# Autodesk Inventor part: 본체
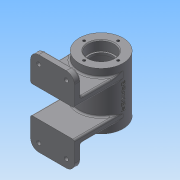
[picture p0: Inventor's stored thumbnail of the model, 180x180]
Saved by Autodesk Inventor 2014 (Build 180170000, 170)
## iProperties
Created: 2017-02
Part Number: 본체
Material: 일반
Document SubType Name: Modeling
Designer: owner
Density: 1 g/cm^3
Appearance: 기본값
Author: owner
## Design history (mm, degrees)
sketch "스케치1"
  geometry: L1 (27, 35)-(0, 35); L2 (0, 35)-(0, -35); L3 (0, -35)-(27, -35); L4 (27, -35)-(27, 35); 1 further point
  constraints: 8 end point, 2 parallel, 1 horizontal, 1 midpoint, 1 perpendicular
  dimensions: "d0" = 70 distance of L1.end L2.end; "d1" = 54 diameter of L4 L2; "d2" = 35 distance from line of point (0, 0) L1
revolve "회전1" sketch "스케치1" stored, may be unused: angle "d3" = 90 deg
node "작업 평면1"
sketch "스케치2"
  geometry: L1 (27, -52)-(-27, -52); L2 (-27, -52)-(-27, 52); L3 (-27, 52)-(27, 52); L4 (27, 52)-(27, -52); 1 further point
  constraints: 8 end point, 2 parallel, 1 horizontal, 1 perpendicular
  dimensions: "d5" = 54 distance between parallel lines of L4 L2; "d6" = 27 distance from line of L4 point (0, 0); "d7" = 52 distance from line of point (0, 0) L1; "d8" = 104 distance between parallel lines of L3 L1
extrude "돌출1" join sketch "스케치2" distance "d9" = 8; taper "d10" = 0 deg
sketch "스케치3"
  geometry: L1 (-27, 52)-(-27, -52) reference; L2 (27, -52)-(27, 52) reference; L3 (-27, 0)-(27, 0); L4 (-27, 17)-(27, 17); L5 (27, 17)-(27, -17); L6 (27, -17)-(-27, -17); L7 (-27, -17)-(-27, 17); 1 further point
  constraints: 10 end point, 2 midpoint, 2 parallel, 2 point on line, 1 horizontal, 1 perpendicular
  dimensions: "d11" = 17 distance from line of L4 point (0, 0); "d12" = 17 distance from line of L6 point (0, 0)
extrude "돌출2" cut sketch "스케치3" stored distance "d13" = 8; taper "d14" = 0 deg
sketch "스케치4"
  geometry: L1 (27, -52)-(27, -17) reference; L2 (-27, -17)-(27, -17); L3 (27, -17)-(27, -25); L4 (27, -25)-(-27, -25); L5 (-27, -25)-(-27, -17); 1 further point
  constraints: 8 end point, 2 parallel, 1 horizontal, 1 perpendicular, 1 point on line
  dimensions: "d15" = 8 distance between parallel lines of L2 L4
extrude "돌출3" join sketch "스케치4" stored distance "d16" = 8; taper "d17" = 0 deg
sketch "스케치5"
  geometry: L1 (-27, -35)-(27, -35) reference; L2 (-27, 35)-(27, 35) reference; L3 (0, -35)-(0, 35); L4 (16, 35)-(0, 35); L5 (0, 35)-(0, 23); L6 (0, 23)-(16, 23); L7 (16, 23)-(16, 35); L8 (0, 23)-(14, 23); L9 (14, 23)-(14, 20); L10 (14, 20)-(0, 20); L11 (0, 20)-(0, 23); L12 (0, 20)-(22, 20); L13 (22, 20)-(22, -20); L14 (22, -20)-(0, -20); L15 (0, -20)-(0, 20); L16 (0, -20)-(14, -20); L17 (14, -20)-(14, -23); L18 (14, -23)-(0, -23); L19 (0, -23)-(0, -20); L20 (0, -23)-(16, -23); L21 (16, -23)-(16, -35); L22 (16, -35)-(0, -35); L23 (0, -35)-(0, -23); 1 further point
  constraints: 42 end point, 10 parallel, 5 horizontal, 5 perpendicular, 3 point on line, 2 midpoint
  dimensions: "d18" = 32 diameter of L21 L3; "d19" = 44 diameter of L13 L3; "d20" = 12 distance between parallel lines of L22 L20; "d21" = 3 distance between parallel lines of L16 L20; "d22" = 28 diameter of L17 L3; "d23" = 40 distance between parallel lines of L10 L16; "d24" = 32 diameter of L7 L3; "d25" = 28 diameter of L9 L3; "d26" = 12 distance between parallel lines of L6 L4
revolve "회전2" sketch "스케치5" stored, may be unused: angle "d27" = 90 deg
fillet "모깎기1" dims "d28" = 10
sketch "스케치6" dims "d29" = 9, "d30" = 9
  geometry: L1 (-12.5, -44.598)-(-17, -47.196); L2 (-17, -47.196)-(-21.5, -44.598); L3 (-21.5, -44.598)-(-21.5, -39.402); L4 (-21.5, -39.402)-(-17, -36.804); L5 (-17, -36.804)-(-12.5, -39.402); L6 (-12.5, -39.402)-(-12.5, -44.598); L7 (21.5, -39.402)-(21.5, -44.598); L8 (21.5, -44.598)-(17, -47.196); L9 (17, -47.196)-(12.5, -44.598); L10 (12.5, -44.598)-(12.5, -39.402); L11 (12.5, -39.402)-(17, -36.804); L12 (17, -36.804)-(21.5, -39.402); C1 r 2.5 at (-17, -42); C2 r 2.5 at (17, -42); A1 r 10 centre (-17, -42) between (-27, -42) and (-17, -52) reference; A2 r 10 centre (17, -42) between (17, -52) and (27, -42) reference; A3 r 10 centre (-17, 42) between (-17, 52) and (-27, 42) reference; A4 r 10 centre (17, 42) between (27, 42) and (17, 52) reference; 8 further points
  constraints: 24 end point, 6 coincident, 3 horizontal alignment, 3 midpoint, 2 centre point, 31 other
  dimensions: "d31" = 5 diameter of C1; "d32" = 5 diameter of C2
extrude "돌출4" cut sketch "스케치6" stored distance "d33" = 8; taper "d34" = 0 deg
extrude "돌출5" cut sketch "스케치6" distance "d35" = 3; taper "d36" = 0 deg
extrude "돌출6" cut sketch "스케치6" distance "d37" = 3; taper "d38" = 0 deg
node "작업 평면2"
sketch "스케치7"
  geometry: L1 (-27, 35)-(27, 35) reference; C1 r 5 at (0, 10); 1 further point
  constraints: 1 centre point, 1 vertical alignment
  dimensions: "d41" = 25 distance from line of L1 C1.centre; "d42" = 10 diameter of C1
extrude "돌출7" join sketch "스케치7" stored distance "d43" = 3; taper "d44" = 0 deg
sketch "스케치8"
  geometry: C1 r 16 at (0, 0) reference; 1 further point
  constraints: 1 vertical alignment
  dimensions: "d45" = 21 distance of C1.centre point (0, 21)
hole "구멍1" sketch "스케치8" at (0, 21) diameter "d46" = 3.242; stored, may be unused: countersink angle "d50" = 90 deg, drill point angle "d52" = 118 deg; dims "d47" = 8, "d48" = 4, "d49" = 2, "d51" = 10
sketch "스케치9"
  geometry: C1 r 5 at (0, 0) reference; 2 further points
  constraints: 1 coincident
hole "구멍2" sketch "스케치9" at (0, 0) diameter "d56" = 5.188; stored, may be unused: countersink angle "d60" = 90 deg, drill point angle "d62" = 118 deg; dims "d57" = 8, "d58" = 4, "d59" = 2, "d61" = 15
sketch "스케치10"
  geometry: L1 (0, 0)-(-16.339, -25.16); L2 (0, 0)-(0, -60.811)
  constraints: 4 end point, 1 vertical
  dimensions: "d63" = 33 deg angle of L2 L1; "d64" = 30 distance of L1.start L1.end
node "작업 평면3"
sketch "스케치11"
  geometry: C1 r 6 at (0, 0); 1 further point
  constraints: 1 centre point, 1 coincident
  dimensions: "d65" = 12 diameter of C1
extrude "돌출8" join sketch "스케치11" stored distance "d66" = 3; taper "d67" = 0 deg
sketch "스케치12"
  geometry: C1 r 6 at (0, 0) reference; 1 further point
  constraints: 1 coincident
hole "구멍3" sketch "스케치12" at (0, 0) diameter "d68" = 5.188; stored, may be unused: countersink angle "d72" = 90 deg, drill point angle "d74" = 118 deg; dims "d69" = 8, "d70" = 4, "d71" = 2, "d73" = 15
node "작업 평면4"
sketch "스케치13"
  geometry: L1 (27, 35)-(27, -35) reference; L2 (-27, 35)-(27, 35) reference; 2 further points
  constraints: 1 other
  dimensions: "d76" = 27 distance from line of L1 point (0, 0); "d77" = 35 distance from line of L2 point (0, 0)
feature "엠보싱1" sketch "스케치13" dims "d78" = 0.5, "d79" = 0
fillet "모깎기2" dims "d80" = 3
fillet "모깎기3" dims "d81" = 0.3
chamfer "모따기1" distance "d82" = 1; stored, may be unused: second distance "d83" = 2, angle "d84" = 45 deg
fillet "모깎기4" dims "d85" = 2
fillet "모깎기7" dims "d88" = 2
fillet "모깎기9" dims "d90" = 2
fillet "모깎기10" dims "d91" = 2
fillet "모깎기11" dims "d92" = 2
fillet "모깎기12" dims "d93" = 2
fillet "모깎기13" dims "d94" = 2
fillet "모깎기14" dims "d95" = 2
fillet "모깎기15" dims "d96" = 2
fillet "모깎기16" dims "d97" = 2
fillet "모깎기17" dims "d98" = 2
node "솔리드1"
mirror "대칭1"
mirror "대칭2"
mirror "대칭3"
pattern_circular "원형 패턴1" dims angle "d54" = 360 deg
mirror "대칭4"
other parameters: "d39" = 32
